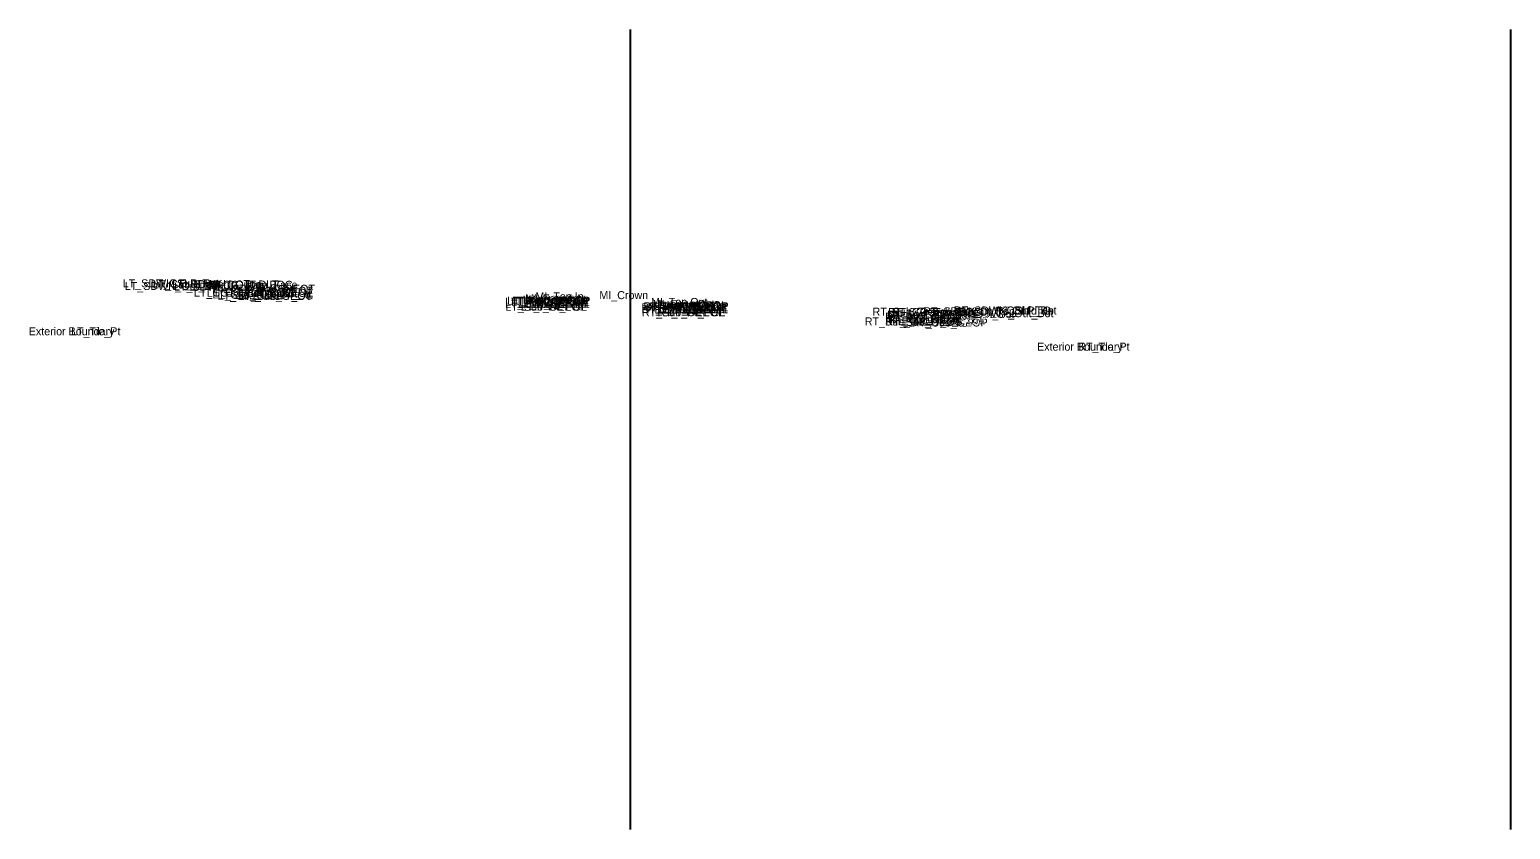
# Model space of a CAD drawing. Extents: x 0 to 6300, y -50 to 9550.
# Drawn here: x 1074.9 to 1260, y 7450 to 7550 of the extents above; entities that cross this region are included whole.
import ezdxf

# ---------------------------------------------------------------- set-up
doc = ezdxf.new("R2010")
doc.units = 0
for name, color, linetype in [('Default', 7, 'Continuous'), ('Prop XS Exc Vertical Line 2', 7, 'Continuous'), ('Prop XS Exc Vertical Line 3', 7, 'Continuous')]:
    doc.layers.add(name, color=color, linetype=linetype)

msp = doc.modelspace()

# ---------------------------------------------------------------- linework, layer by layer
at = {"layer": 'Prop XS Exc Vertical Line 2'}
msp.add_line((1150, 7550), (1150, 7450), dxfattribs=at)
at = {"layer": 'Prop XS Exc Vertical Line 3'}
msp.add_line((1260, 7550), (1260, 7450), dxfattribs=at)

# ---------------------------------------------------------------- texts
at = {"layer": 'Default'}
for s, p in [('LT_SDWK_Out_Top', (1086.58, 7517.78)), ('LT_SDWK_Out_Bot', (1086.83, 7517.44)), ('LT_CSLP_Pnt', (1090.1, 7517.78)), ('LT_Sub_Trench_Out_DLT', (1090.32, 7517.63)), ('LT_SDWK_In_Top', (1092.74, 7517.68)), ('LT_SDWK_In_Bot', (1092.99, 7517.34)), ('LT_CG1_Shelf_Out', (1095.48, 7516.62)), ('LT_CG_Top_BOC', (1096.81, 7517.59)), ('LT_CG_Bot_BOC', (1097.09, 7516.6)), ('LT_CG_Top_Face', (1097.34, 7517.59)), ('LT_Sub_OEOP', (1097.79, 7516.38)), ('LT_CG_Top_Gut', (1097.87, 7517.09)), ('LT_Sub_OEOT_CG', (1098.44, 7516.25)), ('LT_PV2_OEOT', (1100.99, 7516.84)), ('LT_PV3_OEOT', (1100.99, 7516.59)), ('LT_Sub_OEOT', (1101.04, 7516.21)), ('LT_PV1_OEOT', (1101.23, 7517.09)), ('LT_CG_Bot_IE', (1101.34, 7516.5)), ('MI_Top In', (1138.16, 7516.14)), ('MI_Crown', (1146.15, 7516.3)), ('LT_PV2_OEEOP', (1134.36, 7515.47)), ('LT_PV3_OEEOP', (1134.36, 7515.22)), ('LT_Sub_OEEOP', (1134.41, 7514.85)), ('LT_PV1_OEEOP', (1134.6, 7515.6)), ('LT_PV2_IEEOP', (1135.12, 7515.47)), ('LT_PV1_IEEOP', (1135.36, 7515.6)), ('LT_PV2_PGL1', (1135.96, 7515.47)), ('LT_PV3_PGL1', (1135.96, 7515.22)), ('LT_PV2_PGL', (1136.34, 7515.47)), ('LT_PV4_PGL', (1136.34, 7514.85)), ('LT_PV1_PGL', (1136.58, 7515.72)), ('MI_Face In', (1136.88, 7515.89)), ('MI_Bot In', (1138.05, 7515.72)), ('RT_PV2_OEEOP', (1151.42, 7514.79)), ('RT_PV3_OEEOP', (1151.42, 7514.54)), ('RT_Sub_OEEOP', (1151.46, 7514.16)), ('RT_PV1_OEEOP', (1151.66, 7514.91)), ('RT_PV2_IEEOP', (1152.18, 7514.79)), ('RT_PV1_IEEOP', (1152.42, 7514.91)), ('MI_Top Out', (1152.6, 7515.45)), ('MI_Face Out', (1152.81, 7515.2)), ('RT_PV2_PGL1', (1153.02, 7514.79)), ('RT_PV3_PGL1', (1153.02, 7514.54)), ('RT_PV2_PGL', (1153.4, 7514.79)), ('RT_PV4_PGL', (1153.4, 7514.16)), ('RT_PV1_PGL', (1153.63, 7515.04)), ('MI_Bot Out', (1154, 7515.04)), ('RT_Sub_Trench_Out_DLT', (1180.29, 7514.23)), ('RT_CG_Top_Face', (1182.22, 7514.19)), ('RT_CG_Top_BOC', (1182.69, 7514.19)), ('RT_SDWK_In_Top', (1186.62, 7514.28)), ('RT_SDWK_Out_Top', (1190.46, 7514.38)), ('RT_Shld_O', (1195.63, 7514.37)), ('CSLP_Pnt', (1197.04, 7514.38)), ('RT_Sub_OEOT_CG', (1179.32, 7513.01)), ('RT_PV2_OEOT', (1181.87, 7513.6)), ('RT_PV3_OEOT', (1181.87, 7513.35)), ('RT_Sub_OEOT', (1181.92, 7512.97)), ('RT_PV1_OEOT', (1182.11, 7513.85)), ('RT_CG_Bot_IE', (1182.22, 7513.26)), ('RT_CG1_Shelf_Out', (1182.36, 7513.14)), ('RT_CG_Top_Gut', (1182.75, 7513.69)), ('RT_CG_Bot_BOC', (1182.97, 7513.16)), ('RT_Sub_OEOP', (1185.17, 7512.88)), ('RT_SDWK_In_Bot', (1186.87, 7513.94)), ('RT_SDWK_Out_Bot', (1190.71, 7514.04)), ('Exterior Boundary', (1074.84, 7511.78)), ('LT_Tie_Pt', (1080.12, 7511.78)), ('Exterior Boundary', (1200.85, 7509.86)), ('RT_Tie_Pt', (1206.01, 7509.86))]:
    msp.add_text(s, height=1, dxfattribs=at).set_placement(p)

doc.saveas('drawing.dxf')
